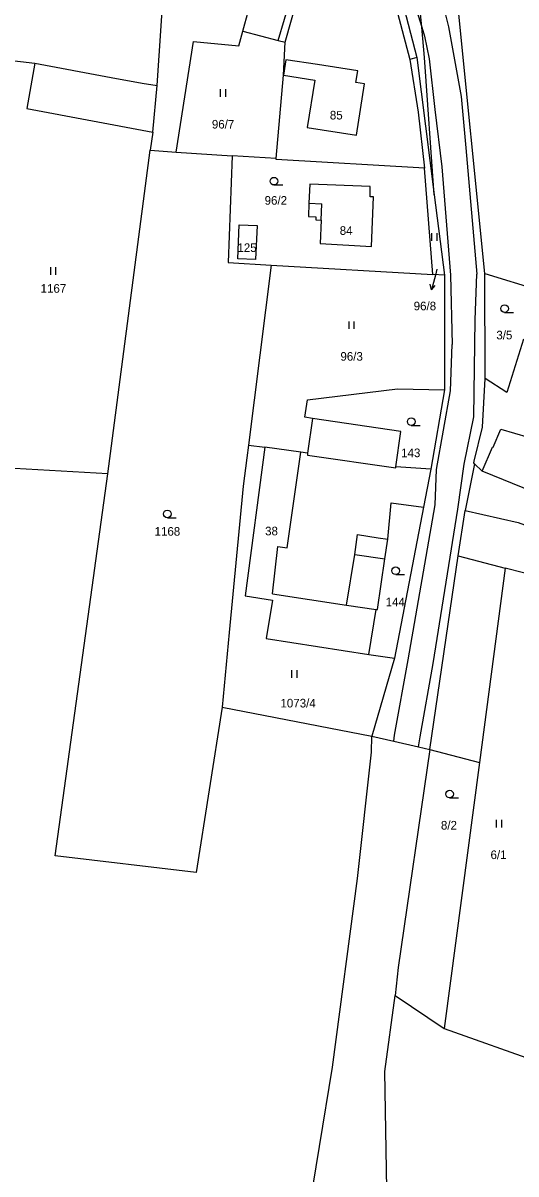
# Model space of a CAD drawing. Extents: x -746176 to -739709, y -1127410 to -1124482.
# Drawn here: x -742243.5 to -742146.3, y -1126433.2 to -1126206.3 of the extents above; entities that cross this region are included whole.
import ezdxf

# ---------------------------------------------------------------- set-up
doc = ezdxf.new("R2010")
doc.units = 0
for name, color, linetype in [('Hranice parcel', 7, 'Continuous'), ('Parcelní čísla', 7, 'Continuous'), ('Pop  PČ popisy', 7, 'Continuous'), ('Vnitřní kresba', 7, 'Continuous'), ('Značky kultur', 7, 'Continuous')]:
    doc.layers.add(name, color=color, linetype=linetype)

msp = doc.modelspace()

# ---------------------------------------------------------------- linework, layer by layer
at = {"layer": 'Hranice parcel'}
for p, q in [((-742191.77, -1126210.15), (-742183.59, -1126181.17)), ((-742152.42, -1126255.73), (-742159.24, -1126187.68)), ((-742165.79, -1126213.16), (-742167.23, -1126213.54)), ((-742165.79, -1126213.16), (-742162.38, -1126240.19)), ((-742217.86, -1126227.84), (-742218.41, -1126231.43)), ((-742226.78, -1126295.24), (-742218.41, -1126231.43)), ((-742218.41, -1126231.43), (-742213.31, -1126231.82)), ((-742213.31, -1126231.82), (-742202.22, -1126232.53)), ((-742193.57, -1126233.02), (-742202.22, -1126232.53)), ((-742162.64, -1126255.9), (-742164.34, -1126234.95)), ((-742162.38, -1126240.19), (-742160.39, -1126256.03)), ((-742194.57, -1126254.06), (-742199.05, -1126289.55)), ((-742194.57, -1126254.06), (-742162.64, -1126255.9)), ((-742160.39, -1126256.03), (-742162.64, -1126255.9)), ((-742160.39, -1126256.03), (-742160.39, -1126278.66)), ((-742152.42, -1126255.73), (-742141.7, -1126259.03)), ((-742152.35, -1126276.44), (-742152.42, -1126255.73)), ((-742160.39, -1126278.66), (-742163.05, -1126294.31)), ((-742199.05, -1126289.55), (-742195.79, -1126289.99)), ((-742154.48, -1126293.27), (-742156.3, -1126302.44)), ((-742163.05, -1126294.31), (-742164.48, -1126301.76)), ((-742164.48, -1126301.76), (-742170.24, -1126331.56)), ((-742157.68, -1126311.4), (-742156.3, -1126302.44)), ((-742163.24, -1126349.58), (-742157.68, -1126311.4)), ((-742157.68, -1126311.4), (-742148.42, -1126313.8)), ((-742131.46, -1126318.2), (-742148.42, -1126313.8)), ((-742175.26, -1126330.82), (-742170.24, -1126331.56)), ((-742170.24, -1126331.56), (-742174.68, -1126346.91)), ((-742204.22, -1126341.19), (-742174.68, -1126346.91)), ((-742170.12, -1126398.06), (-742160.44, -1126404.55)), ((-742160.44, -1126404.55), (-742122.15, -1126418.14))]:
    msp.add_line(p, q, dxfattribs=at)
for points in [[(-742184.05, -1126178.64), (-742173.99, -1126190.38), (-742168.81, -1126201.73), (-742165.79, -1126213.16)], [(-742162.38, -1126240.19), (-742164.29, -1126213.12), (-742164.85, -1126207.18), (-742165.74, -1126197.73), (-742175.6, -1126184.38), (-742178.19, -1126182.62), (-742184.05, -1126178.64)], [(-742183.59, -1126181.17), (-742175.14, -1126191.34), (-742170.25, -1126202.12), (-742167.23, -1126213.54)], [(-742217.86, -1126227.84), (-742217.03, -1126218.63), (-742215.44, -1126195.1), (-742214.95, -1126195.15), (-742214.53, -1126192.26)], [(-742213.31, -1126231.82), (-742209.89, -1126210.01), (-742200.95, -1126210.87), (-742200.14, -1126207.94), (-742193.14, -1126209.82), (-742191.77, -1126210.15)], [(-742193.57, -1126233.02), (-742192.14, -1126216.64), (-742191.77, -1126210.15)], [(-742246.8, -1126213.59), (-742241.16, -1126214.28), (-742242.7, -1126223.21), (-742217.86, -1126227.84)], [(-742191.68, -1126213.6), (-742192.14, -1126216.64), (-742185.92, -1126217.59), (-742187.46, -1126226.94), (-742177.72, -1126228.47), (-742176.15, -1126218.34), (-742177.82, -1126218.09), (-742177.47, -1126215.78), (-742185.42, -1126214.55), (-742191.68, -1126213.6)], [(-742167.23, -1126213.54), (-742165.55, -1126223.94), (-742164.34, -1126234.95)], [(-742202.22, -1126232.53), (-742203.02, -1126253.58), (-742194.57, -1126254.06)], [(-742164.34, -1126234.95), (-742193.54, -1126233.25), (-742193.57, -1126233.02)], [(-742185.73, -1126244.55), (-742185.76, -1126245.16), (-742184.7, -1126245.2), (-742184.9, -1126249.82), (-742174.78, -1126250.38), (-742174.35, -1126240.63), (-742175.05, -1126240.62), (-742175.01, -1126238.6), (-742186.93, -1126238.09), (-742187.1, -1126241.89), (-742187.21, -1126244.49), (-742185.73, -1126244.55)], [(-742200.86, -1126246.11), (-742197.3, -1126246.29), (-742197.64, -1126252.97), (-742201.12, -1126252.84), (-742200.86, -1126246.11)], [(-742226.78, -1126295.24), (-742256.74, -1126293.53), (-742253.45, -1126270.36)], [(-742144.79, -1126268.68), (-742148.06, -1126279.2), (-742152.35, -1126276.44)], [(-742154.48, -1126293.27), (-742154.57, -1126293.04), (-742154.53, -1126292.75), (-742152.88, -1126286), (-742152.35, -1126276.44)], [(-742186.42, -1126284.28), (-742187.9, -1126284.06), (-742187.39, -1126280.61), (-742169.61, -1126278.45), (-742160.39, -1126278.66)], [(-742186.42, -1126284.28), (-742187.38, -1126291.11), (-742188.73, -1126290.93), (-742195.79, -1126289.99)], [(-742163.05, -1126294.31), (-742169.96, -1126293.86), (-742168.98, -1126286.85), (-742186.42, -1126284.28)], [(-742199.05, -1126289.55), (-742199.37, -1126292.03), (-742200.07, -1126297.63), (-742202.82, -1126326.51), (-742204.22, -1126341.19)], [(-742195.79, -1126289.99), (-742199.7, -1126319.29), (-742194.31, -1126320.11), (-742195.53, -1126327.65), (-742175.26, -1126330.82)], [(-742098.16, -1126314.66), (-742107.1, -1126311.81), (-742124.49, -1126306.28), (-742152.92, -1126294.67), (-742154.48, -1126293.27)], [(-742204.22, -1126341.19), (-742209.35, -1126373.83), (-742237.12, -1126370.54), (-742226.78, -1126295.24)], [(-742175.26, -1126330.82), (-742173.87, -1126321.93), (-742173.57, -1126321.97), (-742172.11, -1126311.98), (-742171.53, -1126308.09), (-742170.89, -1126300.93), (-742164.48, -1126301.76)], [(-742156.3, -1126302.44), (-742145.81, -1126304.8), (-742128.49, -1126311.19)], [(-742148.42, -1126313.8), (-742153.49, -1126352.12), (-742160.44, -1126404.55)], [(-742187.6, -1126443.43), (-742182.48, -1126412.17), (-742177.55, -1126374.98), (-742174.74, -1126350.1), (-742174.68, -1126346.91)], [(-742174.68, -1126346.91), (-742170.38, -1126347.91), (-742165.47, -1126349.06), (-742163.24, -1126349.58)], [(-742163.24, -1126349.58), (-742169.48, -1126392.54), (-742170.12, -1126398.06)], [(-742133.47, -1126503.52), (-742138.17, -1126495.9), (-742152.98, -1126479.01), (-742161.38, -1126468.51), (-742167.25, -1126457.12), (-742171.72, -1126436.22), (-742172.13, -1126413.04), (-742170.12, -1126398.06)]]:
    msp.add_lwpolyline(points, dxfattribs=at)
at = {"layer": 'Pop  PČ popisy'}
for p, q in [((-742161.85, -1126254.86), (-742162.16, -1126256.02)), ((-742162.16, -1126256.02), (-742162.937, -1126258.919)), ((-742162.937, -1126258.919), (-742163.161, -1126257.822)), ((-742162.937, -1126258.919), (-742162.194, -1126258.081))]:
    msp.add_line(p, q, dxfattribs=at)
at = {"layer": 'Vnitřní kresba'}
for p, q in [((-742193.14, -1126209.82), (-742184.49, -1126180.09)), ((-742161.57, -1126198.94), (-742159.55, -1126207.12)), ((-742166.82, -1126200.85), (-742164.85, -1126207.18)), ((-742200.14, -1126207.94), (-742199, -1126203.86)), ((-742164.85, -1126207.18), (-742164.3, -1126208.95)), ((-742159.55, -1126207.12), (-742157.09, -1126220.82)), ((-742164.3, -1126208.95), (-742163.42, -1126213.41)), ((-742163.42, -1126213.41), (-742162.27, -1126223.42)), ((-742241.16, -1126214.28), (-742226.13, -1126217.11)), ((-742226.13, -1126217.11), (-742220, -1126218.18)), ((-742220, -1126218.18), (-742217.03, -1126218.63)), ((-742157.09, -1126220.82), (-742156.14, -1126230.96)), ((-742162.27, -1126223.42), (-742160.86, -1126234.67)), ((-742156.14, -1126230.96), (-742154, -1126255.84)), ((-742160.86, -1126234.67), (-742159.19, -1126256.08)), ((-742187.1, -1126241.89), (-742184.56, -1126242)), ((-742184.7, -1126245.2), (-742184.56, -1126242)), ((-742159.19, -1126256.08), (-742158.88, -1126269.7)), ((-742154.3, -1126264.85), (-742154, -1126255.84)), ((-742154.56, -1126283.96), (-742154.3, -1126264.85)), ((-742159.2, -1126278.85), (-742158.88, -1126269.7)), ((-742161.92, -1126294.39), (-742159.2, -1126278.85)), ((-742156.48, -1126293.32), (-742154.56, -1126283.96)), ((-742150.78, -1126289.99), (-742149.27, -1126286.44)), ((-742149.27, -1126286.44), (-742137.57, -1126289.85)), ((-742191.36, -1126309.81), (-742188.73, -1126290.93)), ((-742187.38, -1126291.11), (-742187.36, -1126291.53)), ((-742152.92, -1126294.67), (-742150.91, -1126289.93)), ((-742150.91, -1126289.93), (-742150.78, -1126289.99)), ((-742187.36, -1126291.53), (-742169.98, -1126294)), ((-742157.74, -1126302.18), (-742156.48, -1126293.32)), ((-742169.98, -1126294), (-742169.96, -1126293.86)), ((-742162.18, -1126301.35), (-742161.92, -1126294.39)), ((-742167.55, -1126331.85), (-742162.18, -1126301.35)), ((-742162.6, -1126332.62), (-742157.74, -1126302.18)), ((-742178.07, -1126311.14), (-742177.5, -1126307.2)), ((-742177.5, -1126307.2), (-742173.42, -1126307.81)), ((-742173.42, -1126307.81), (-742171.53, -1126308.09)), ((-742194.3, -1126318.85), (-742193.22, -1126309.55)), ((-742193.22, -1126309.55), (-742191.36, -1126309.81)), ((-742179.7, -1126321.11), (-742178.07, -1126311.14)), ((-742178.07, -1126311.14), (-742172.11, -1126311.98)), ((-742194.3, -1126318.85), (-742179.7, -1126321.11)), ((-742179.7, -1126321.11), (-742173.87, -1126321.93)), ((-742170.22, -1126346.76), (-742167.55, -1126331.85)), ((-742165.18, -1126347.04), (-742162.6, -1126332.62)), ((-742170.38, -1126347.91), (-742170.22, -1126346.76)), ((-742165.47, -1126349.06), (-742165.18, -1126347.04)), ((-742163.24, -1126349.58), (-742153.49, -1126352.12))]:
    msp.add_line(p, q, dxfattribs=at)
at = {"layer": 'Značky kultur'}
for p, q in [((-742204.511, -1126220.9), (-742204.511, -1126219.4)), ((-742203.51, -1126220.9), (-742203.51, -1126219.4)), ((-742194.013, -1126238.27), (-742192.263, -1126238.27)), ((-742162.841, -1126249.27), (-742162.841, -1126247.77)), ((-742161.84, -1126249.27), (-742161.84, -1126247.77)), ((-742238.021, -1126255.97), (-742238.021, -1126254.47)), ((-742237.02, -1126255.97), (-742237.02, -1126254.47)), ((-742148.513, -1126263.38), (-742146.763, -1126263.38)), ((-742179.161, -1126266.66), (-742179.161, -1126265.16)), ((-742178.16, -1126266.66), (-742178.16, -1126265.16)), ((-742166.933, -1126285.68), (-742165.183, -1126285.68)), ((-742215.023, -1126303.86), (-742213.273, -1126303.86)), ((-742169.993, -1126315.08), (-742168.243, -1126315.08)), ((-742190.451, -1126335.41), (-742190.451, -1126333.91)), ((-742189.45, -1126335.41), (-742189.45, -1126333.91)), ((-742159.353, -1126359.09), (-742157.603, -1126359.09)), ((-742150.091, -1126364.91), (-742150.091, -1126363.41)), ((-742149.09, -1126364.91), (-742149.09, -1126363.41))]:
    msp.add_line(p, q, dxfattribs=at)
for centre in [(-742194.013, -1126237.52), (-742148.513, -1126262.63), (-742166.933, -1126284.93), (-742215.023, -1126303.11), (-742169.993, -1126314.33), (-742159.353, -1126358.34)]:
    msp.add_circle(centre, 0.75, dxfattribs=at)

# ---------------------------------------------------------------- texts
at = {"layer": 'Parcelní čísla'}
for s, p in [('96/7', (-742206.241, -1126227.15)), ('85', (-742182.972, -1126225.36)), ('96/2', (-742195.841, -1126242.16)), ('84', (-742181.022, -1126248.11)), ('125', (-742201.204, -1126251.48)), ('1167', (-742240.017, -1126259.52)), ('96/8', (-742166.442, -1126262.98)), ('3/5', (-742150.14, -1126268.71)), ('96/3', (-742180.891, -1126272.91)), ('143', (-742168.914, -1126291.93)), ('1168', (-742217.537, -1126307.41)), ('38', (-742195.742, -1126307.34)), ('144', (-742171.974, -1126321.33)), ('1073/4', (-742192.715, -1126341.27)), ('8/2', (-742161.068, -1126365.34)), ('6/1', (-742151.288, -1126371.16))]:
    msp.add_text(s, height=1.7, dxfattribs=at).set_placement(p)

doc.saveas('drawing.dxf')
